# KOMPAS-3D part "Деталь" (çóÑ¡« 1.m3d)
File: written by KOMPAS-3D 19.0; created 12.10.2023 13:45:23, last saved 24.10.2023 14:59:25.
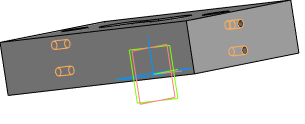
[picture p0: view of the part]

Document properties: Автор: admin; Организация: Hewlett-Packard Company; Полное имя файла: C:\Users\Petrenko-VE\Desktop\пресса 50 т\оправка выпресовки втулок\Звено_1.m3d

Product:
- Part/product: Деталь
    Масса: 12.687

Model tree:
1. Эскиз:1
2. Элемент выдавливания:1
     Расстояние 1 = 50
3. Эскиз:2  (with: Элемент выдавливания:1)
4. Элемент выдавливания:2
     Расстояние 2 = 5
5. Скругление:1  (with: Элемент выдавливания:2)
     Радиус = 20
6. Скругление:2  (with: Элемент выдавливания:2)
     Радиус = 20
7. Скругление:3  (with: Элемент выдавливания:2)
     Радиус = 20
8. Эскиз:3  (with: Элемент выдавливания:2)
9. Элемент выдавливания:3
     Расстояние 2 = 45
10. Эскиз:4  (with: Элемент выдавливания:1)
11. Элемент выдавливания:4
     Расстояние 2 = 50
12. Эскиз:5  (with: Элемент выдавливания:1)
13. Элемент выдавливания:5
     Расстояние 2 = 30
14. Эскиз:6  (with: Элемент выдавливания:1)
15. Элемент выдавливания:6
     Расстояние 2 = 30
16. Условное изображение резьбы:1  (with: Элемент выдавливания:6)  (labels: M8; cil0_24705-2004 coarse)
     Длина резьбы = 10; Шаг резьбы = 1.25; Номинальный диаметр резьбы = 8
17. Подгонка:1  (with: Элемент выдавливания:6)
18. Условное изображение резьбы:2  (with: Элемент выдавливания:6)  (labels: M8; cil0_24705-2004 coarse)
     Длина резьбы = 16.1573; Шаг резьбы = 1.25; Номинальный диаметр резьбы = 8
19. Подгонка:2  (with: Элемент выдавливания:6)
20. Условное изображение резьбы:3  (with: Элемент выдавливания:6)  (labels: M8; cil0_24705-2004 coarse)
     Длина резьбы = 16.1573; Шаг резьбы = 1.25; Номинальный диаметр резьбы = 8
21. Подгонка:3  (with: Элемент выдавливания:6)
22. Условное изображение резьбы:4  (with: Элемент выдавливания:5)  (labels: M8; cil0_24705-2004 coarse)
     Длина резьбы = 16.1414; Шаг резьбы = 1.25; Номинальный диаметр резьбы = 8
23. Подгонка:4  (with: Элемент выдавливания:5)
24. Условное изображение резьбы:5  (with: Элемент выдавливания:5)  (labels: M8; cil0_24705-2004 coarse)
     Длина резьбы = 16.1414; Шаг резьбы = 1.25; Номинальный диаметр резьбы = 8
25. Подгонка:5  (with: Элемент выдавливания:5)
